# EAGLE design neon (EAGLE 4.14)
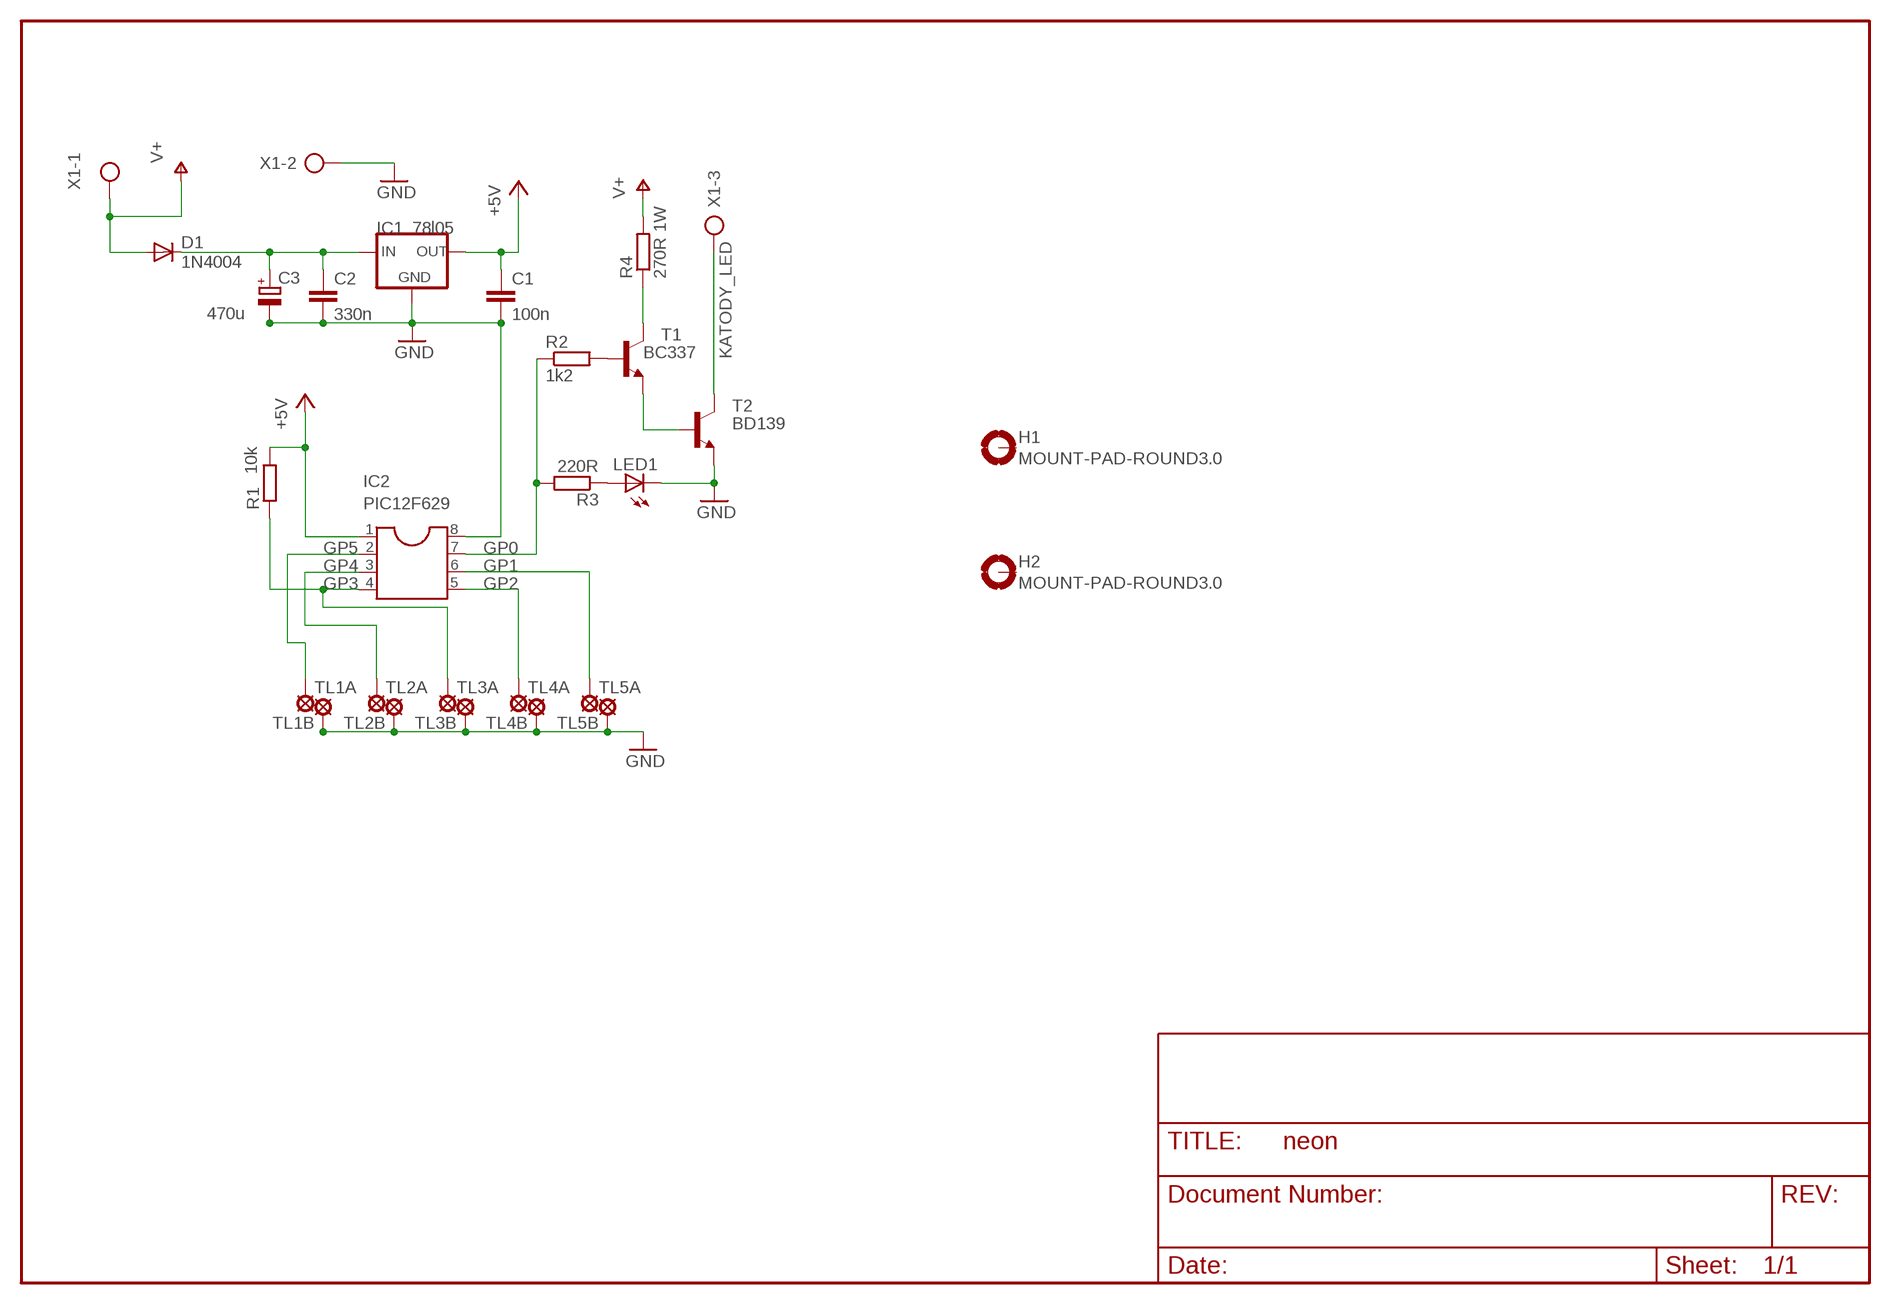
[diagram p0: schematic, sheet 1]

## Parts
C1  100n  C-EU050-030X075  [C050-030X075]
C2  330n  C-EU050-030X075  [C050-030X075]
C3  470u  CPOL-EUE5-8.5  [E5-8,5]
D1  1N4004  [DO41-10]
H1  MOUNT-PAD-ROUND3.0  [3,0-PAD]
H2  MOUNT-PAD-ROUND3.0  [3,0-PAD]
IC1  78l05  78LXX  [78LXX]
IC2  PIC12F629  DIL8S  [SOCKED-08]
LED1  LED5MM  [LED5MM]
R1  10k  R-EU_0207/10  [0207/10]
R2  1k2  R-EU_0207/10  [0207/10]
R3  220R  R-EU_0207/10  [0207/10]
R4  270R 1W  R-EU_0411/15  [0411/15]
T1  BC337  [TO92]
T2  BD139  [TO126]
TL1A  LSP10  [LSP10]
TL1B  LSP10  [LSP10]
TL2A  LSP10  [LSP10]
TL2B  LSP10  [LSP10]
TL3A  LSP10  [LSP10]
TL3B  LSP10  [LSP10]
TL4A  LSP10  [LSP10]
TL4B  LSP10  [LSP10]
TL5A  LSP10  [LSP10]
TL5B  LSP10  [LSP10]
X1  AK300/3  [AK300/3]

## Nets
+5V: C1.1 IC1.OUT IC2.1 R1.2
GND: C1.2 C2.2 C3.- IC1.GND IC2.8 LED1.K(C) T2.1(E) TL1A.MP TL2A.MP TL3A.MP TL4A.MP TL5A.MP X1.2
GP0: IC2.7 R2.1 R3.2
GP1: IC2.6 TL5B.MP
GP2: IC2.5 TL4B.MP
GP3: IC2.4 R1.1 TL3B.MP
GP4: IC2.3 TL2B.MP
GP5: IC2.2 TL1B.MP
KATODY_LED: T2.2(C) X1.3
N$2: C2.1 C3.+ D1.C IC1.IN
N$5: T1.1(E) T2.3(B)
N$6: R2.2 T1.2(B)
N$7: LED1.A R3.1
N$8: R4.1 T1.3(C)
V+: D1.A R4.2 X1.1
Unconnected: H1.B3,0(MOUNT) H2.B3,0(MOUNT)

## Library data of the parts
C1 C2 = rcl:C-EU: CAPACITOR, European symbol
C3 = rcl:CPOL-EU: POLARIZED CAPACITOR, European symbol
D1 = diode:1N4004: DIODE
H1 H2 = holes:MOUNT-PAD-ROUND: MOUNTING PAD, round
IC1 = v-reg:78LXX: VOLTAGE REGULATOR
IC2 = ic-package:DIL8: Dual In Line
LED1 = led:LED: LED
R1-R4 = rcl:R-EU_: RESISTOR, European symbol
T1 = transistor-npn:BC337*: NPN Transistor
T2 = transistor-npn:BD139*: NPN Transistor
TL1A TL1B TL2A TL2B TL3A TL3B TL4A TL4B TL5A TL5B = solpad:LSP10: SOLDER PAD
X1 = con-ptr500:AK300/3: CONNECTOR

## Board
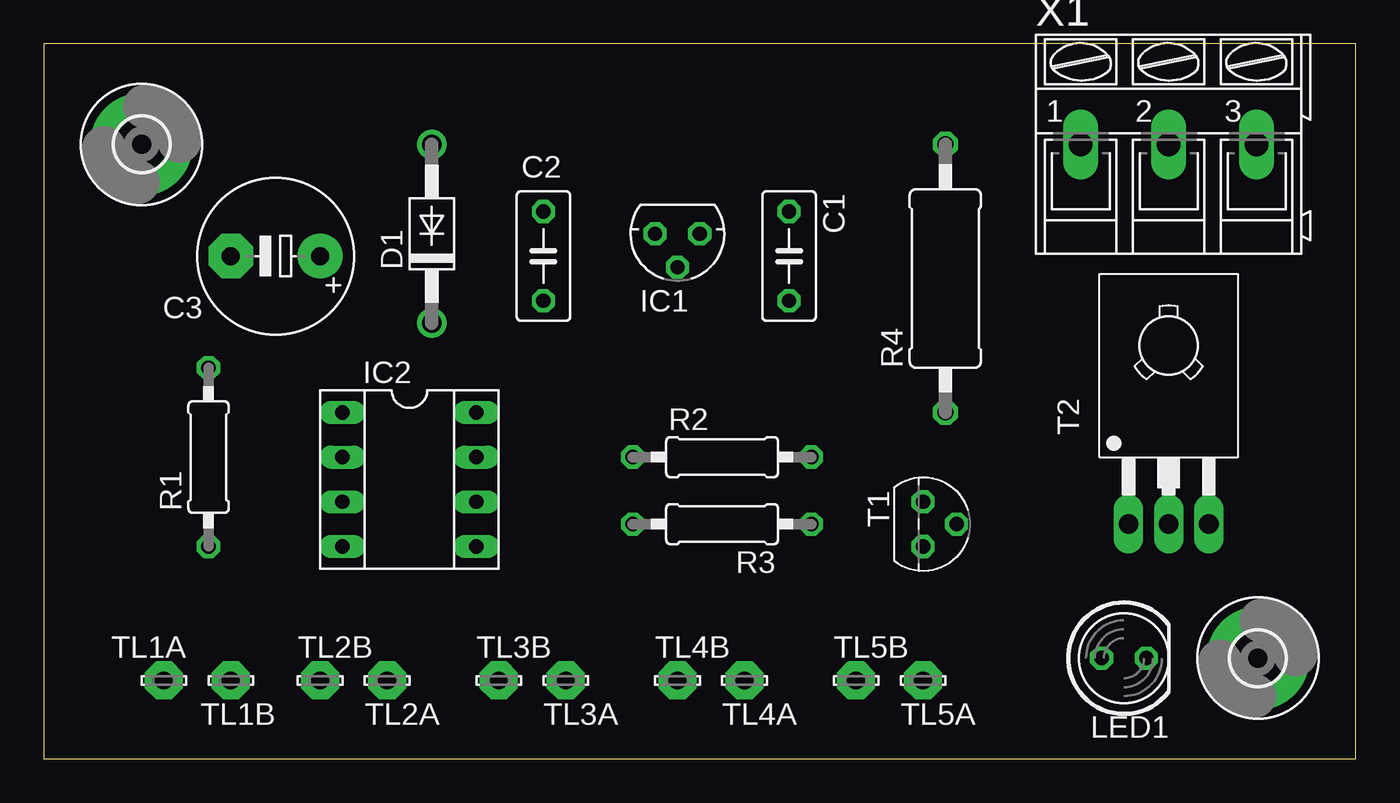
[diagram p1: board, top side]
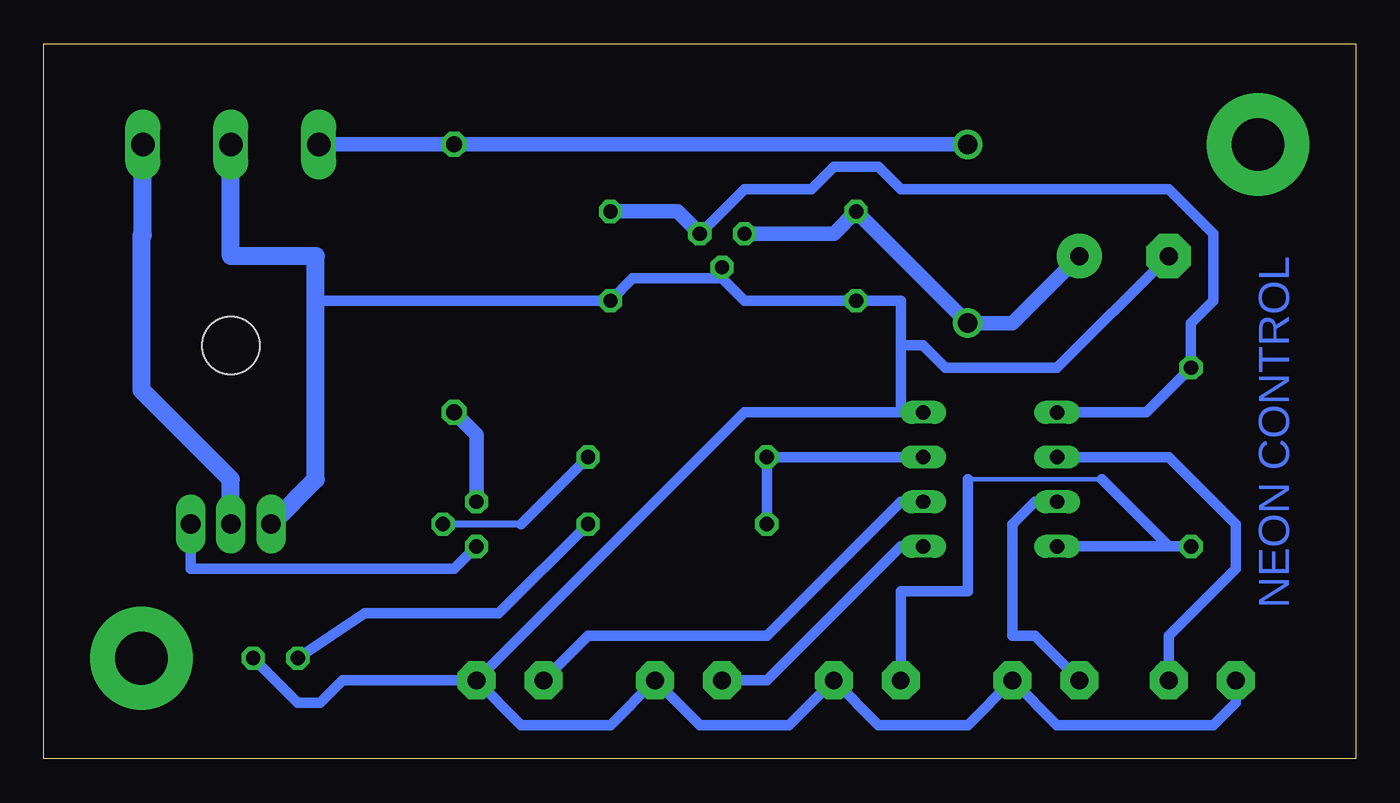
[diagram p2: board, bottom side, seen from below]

Size 74.6 x 40.63 mm. Coordinates in mm from the lower left corner, seen from the top.
Outline: 0,0 74.6,0 74.6,40.63 0,40.63 0,0
Copper layers (1*16): Top 0.035mm / dielectric 1.5mm / Bottom 0.035mm
Design rules "default": minimum track width 10mil, minimum drill 24mil, track to track 8mil, track to pad 8mil, pad to pad 8mil, via to via 8mil, smd to smd 8mil, copper to edge 40mil, drill to drill 8mil, minimum pad ring 10mil, minimum via ring 8mil, stop-mask expansion 4mil, vias tented up to drill 0mil, thermal gap 10mil

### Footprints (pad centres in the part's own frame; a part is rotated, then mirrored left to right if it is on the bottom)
C050-030X075 = drill 0.813 octagon: 1 -2.54,0; 2 2.54,0
E5-8,5 = drill 1.016 pad 2.54 round: + -2.54,0 | drill 1.016 pad 2.54 octagon: - 2.54,0
DO41-10 = drill 1.118 round: A 5.08,0; C -5.08,0
3,0-PAD = drill 3 pad 5.842 round: B3,0 0,0
78LXX = drill 0.813 octagon: GND 0,1.905; IN 1.27,0; OUT -1.27,0
SOCKED-08 = drill 0.813 long: 1 -3.81,-3.81; 2 -1.27,-3.81; 3 1.27,-3.81; 4 3.81,-3.81; 5 3.81,3.81; 6 1.27,3.81; 7 -1.27,3.81; 8 -3.81,3.81
LED5MM = drill 0.813 octagon: A -1.27,0; K 1.27,0
0207/10 = drill 0.813 octagon: 1 -5.08,0; 2 5.08,0
0411/15 = drill 0.914 octagon: 1 -7.62,0; 2 7.62,0
TO92 = drill 0.813 octagon: 1 1.27,0; 2 0,1.905; 3 -1.27,0
TO126 = drill 1.118 long: 1 -2.286,-5.08; 2 0,-5.08; 3 2.286,-5.08 | hole 3.302: 0,5.08
LSP10 = drill 1.016 pad 2.159 octagon: MP 0,0
AK300/3 = drill 1.321 long: 1 -5.004,0; 2 0,0; 3 5.004,0

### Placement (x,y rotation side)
C1  42.38,28.57 270 top
C2  28.41,28.57 270 top
C3  13.17,28.57 180 top
D1  22.06,29.84 90 top
H1  5.55,34.92 0 top
H2  69.05,5.71 0 top
IC1  36.03,29.84 180 top
IC2  20.79,15.87 270 top
LED1  61.43,5.71 0 top
R1  9.36,17.14 90 top
R2  38.57,17.14 0 top
R3  38.57,13.33 180 top
R4  51.27,27.3 90 top
T1  50,13.33 270 top
T2  63.97,18.41 0 top
TL1A  6.82,4.44 180 top
TL1B  10.63,4.44 180 top
TL2A  19.52,4.44 0 top
TL2B  15.71,4.44 0 top
TL3A  29.68,4.44 0 top
TL3B  25.87,4.44 0 top
TL4A  39.84,4.44 0 top
TL4B  36.03,4.44 0 top
TL5A  50,4.44 0 top
TL5B  46.19,4.44 0 top
X1  63.97,34.92 0 top

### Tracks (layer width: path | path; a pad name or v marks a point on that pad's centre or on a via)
+5V
  Bottom 0.61: IC2.1 11.9,19.68 R1.2 9.36,24.76 8.09,26.03 8.09,29.84 10.63,32.38 25.87,32.38 27.14,33.65 29.68,33.65 30.95,32.38 34.76,32.38 IC1.OUT
  Bottom 0.813: C1.1 38.57,31.11 IC1.OUT
GND
  Bottom 0.254: 58.89,26.03 59.14,15.87
  Bottom 0.61: TL1A.MP 6.82,3.17 8.09,1.9 16.98,1.9 TL2A.MP 22.06,1.9 27.14,1.9 TL3A.MP 32.22,1.9 37.3,1.9 TL4A.MP 42.38,1.9 47.46,1.9 TL5A.MP | TL5A.MP 57.62,4.44 58.89,3.17 60.16,3.17 LED1.K | 36.03,27.3 41.11,27.3 C1.2 58.89,26.03 | 25.87,23.49 25.87,26.03 C2.2 34.76,26.03 36.03,27.3 | 25.87,19.68 25.87,23.49 | C3.- 16.98,22.22 23.33,22.22 24.6,23.49 25.87,23.49 | 36.03,27.3 IC1.GND | TL5A.MP 34.76,19.68 25.87,19.68 | 25.87,19.68 IC2.8
  Bottom 1.016: T2.1 59.14,15.87 59.14,28.57 63.97,28.57 X1.2
GP0
  Bottom 0.61: IC2.7 R2.1 R3.2
GP1
  Bottom 0.61: TL5B.MP 43.65,6.98 33.49,6.98 25.87,14.6 IC2.6
GP2
  Bottom 0.61: TL4B.MP 33.49,4.44 25.87,12.06 IC2.5
GP3
  Bottom 0.254: 14.44,15.87 22.06,15.87
  Bottom 0.61: R1.1 10.63,12.06 | 10.63,12.06 IC2.4 | TL3B.MP 25.87,9.52 22.06,9.52 22.06,15.87 | 10.63,12.06 14.44,15.87
GP4
  Bottom 0.61: TL2B.MP 18.25,6.98 19.52,6.98 19.52,13.33 18.25,14.6 IC2.3
GP5
  Bottom 0.61: TL1B.MP 10.63,6.98 6.82,10.79 6.82,13.33 10.63,17.14 IC2.2
KATODY_LED
  Bottom 1.016: X1.3 68.97,29.76 69.05,29.76 69.05,20.95 63.97,15.87 T2.2
N$2
  Bottom 0.813: C3.+ 19.52,24.76 D1.C C2.1 29.68,29.84 IC1.IN
N$5
  Bottom 0.61: T1.1 51.27,10.79 66.26,10.79 T2.3
N$6
  Bottom 0.406: 47.46,13.33 T1.2
  Bottom 0.61: R2.2 47.46,13.33
N$7
  Bottom 0.61: R3.1 48.73,8.25 56.35,8.25 LED1.A
N$8
  Bottom 0.813: R4.1 50,18.41 T1.3
V+
  Bottom 0.813: X1.1 R4.2 D1.A

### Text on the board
Bottom: NEON CONTROL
